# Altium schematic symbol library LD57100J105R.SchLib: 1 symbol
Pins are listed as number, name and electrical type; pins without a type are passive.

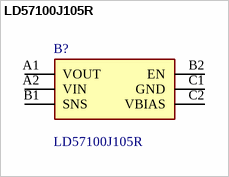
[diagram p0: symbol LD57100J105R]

## LD57100J105R
designator B?
Linear Voltage Regulator IC Positive Fixed 1 Output 1A 6-FlipChip (0.78x1.18); Manufacturer_Name: STMicroelectronics; Geometry.Height: 0.361mm
footprint BGA6C40P2X3_78X118X36
pins: A1 VOUT, A2 VIN, B1 SNS, B2 EN, C1 GND, C2 VBIAS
